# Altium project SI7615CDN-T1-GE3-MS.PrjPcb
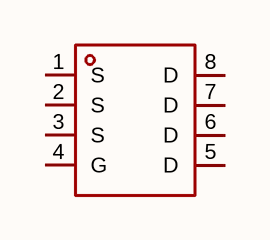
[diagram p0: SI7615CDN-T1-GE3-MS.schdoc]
1 sheet, 1 parts. Net scope: global (net labels, ports and power ports of the same name join across sheets).

## Sheet SI7615CDN-T1-GE3-MS.schdoc
size 127 x 101 mm

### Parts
Q?  si7615cdn-t1-ge3-ms  [POWERPAK-1212-8_L3.0-W3.0-P0.65-LS3.3-BL]  (value not drawn)

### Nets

Not connected (* = marked no-connect by the designer): Q? 1(S) 2(S) 3(S) 4(G) 5(D) 6(D) 7(D) 8(D)

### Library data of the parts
Q? = si7615cdn-t1-ge3-ms: 数量:1个P沟道;漏源电压(Vdss):20V;连续漏极电流(Id):60A;导通电阻(RDS(on)):7mΩ@4.5V;耗散功率(Pd):22W;阈值电压(Vgs(th)):700mV;; Manufacturer: MSKSEMI(美森科); AddInBom: yes; ModelId: 74fc8db97a8d4d328d7f3b4acba39a5e; ModelTransform: 129.921,129.921,0,0,0,0,0,0,0; Number: 1个P沟道; Drain to Source Voltage: 20V; Current - Continuous Drain(Id): 60A; Pd - Power Dissipation: 22W; Gate Threshold Voltage (Vgs(th)): 700mV; Gate Charge(Qg): 35nC; Input Capacitance(Ciss): 2.8nF; Reverse Transfer Capacitance (Crss@Vds): 590pF; Type: P沟道; Output Capacitance(Coss): 690pF; Vgs: ±12V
